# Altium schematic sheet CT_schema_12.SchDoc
size 389 x 385 mm
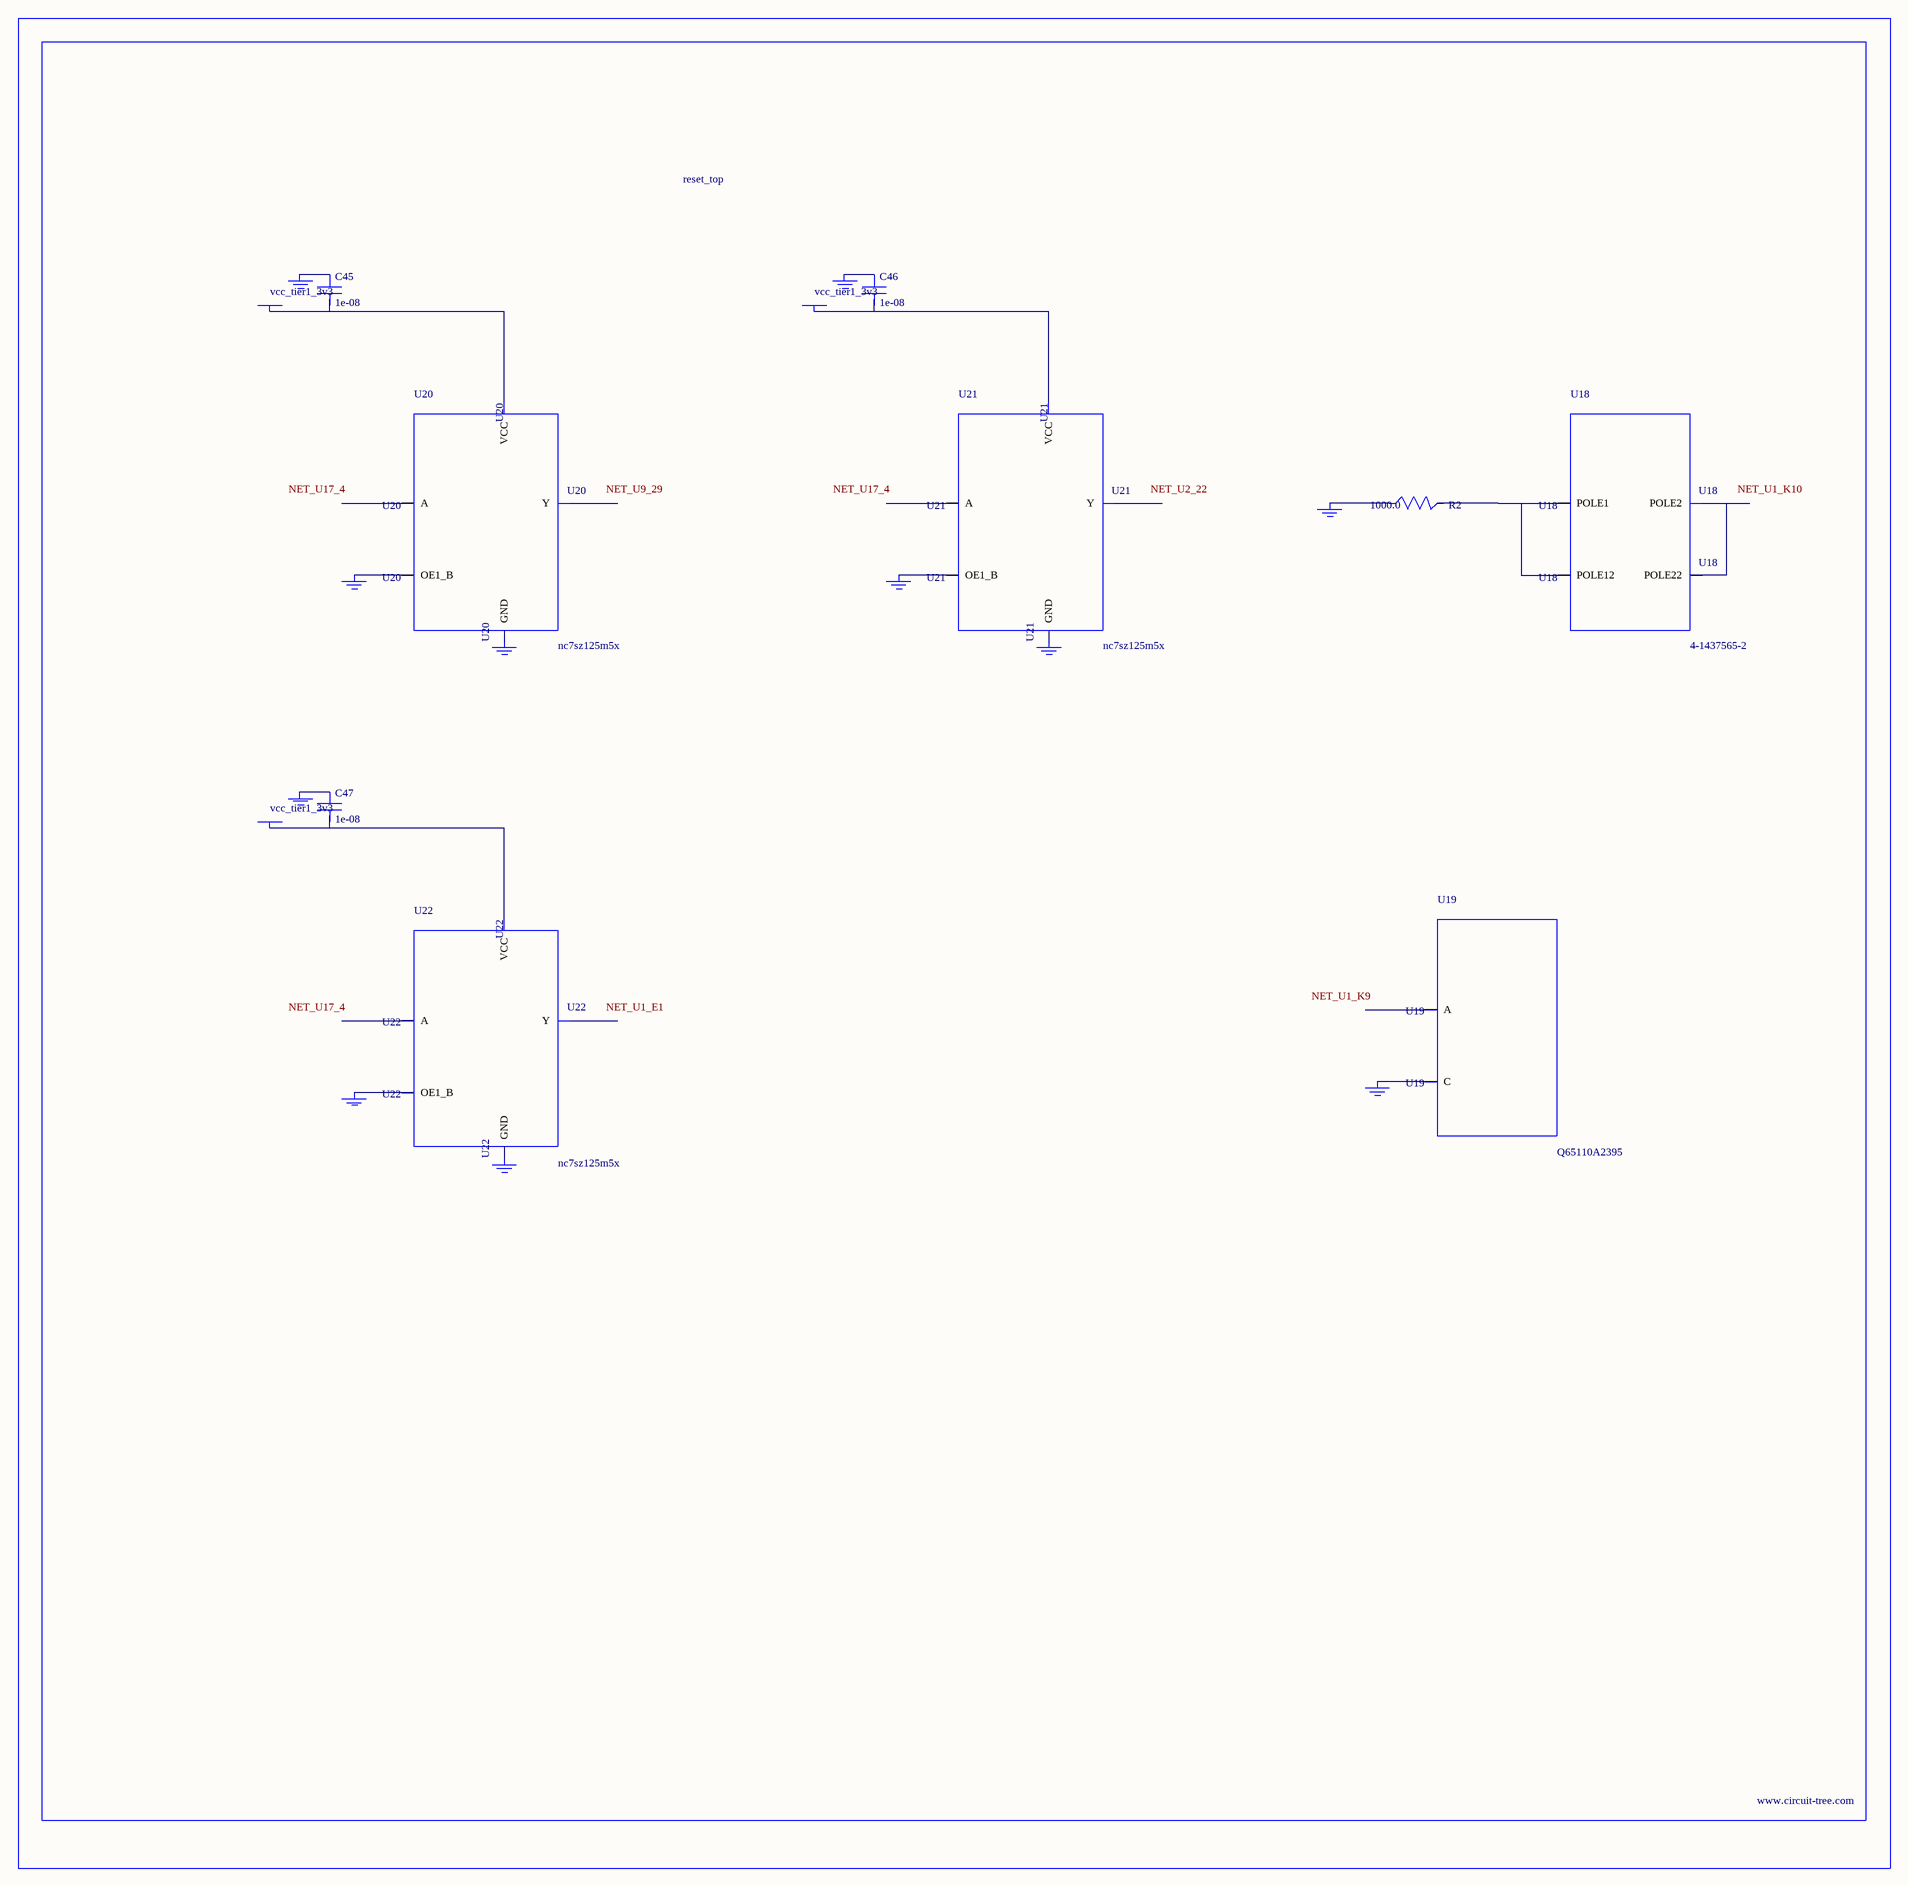
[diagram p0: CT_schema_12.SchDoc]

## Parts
BORDER11  (no value)
C45  1e-08  [C0402]
C46  1e-08  [C0402]
C47  1e-08  [C0402]
GND_INSTANCE_11_0  (no value)
GND_INSTANCE_11_1  (no value)
GND_INSTANCE_11_2  (no value)
GND_INSTANCE_11_3  (no value)
GND_INSTANCE_11_4  (no value)
GND_INSTANCE_11_5  (no value)
GND_INSTANCE_11_6  (no value)
GND_INSTANCE_11_7  (no value)
GND_INSTANCE_11_8  (no value)
GND_INSTANCE_11_9  (no value)
GND_INSTANCE_11_10  (no value)
POWER_INSTANCE_11_0  vcc_tier1_3v3
POWER_INSTANCE_11_1  vcc_tier1_3v3
POWER_INSTANCE_11_2  vcc_tier1_3v3
R2  1000.0  [R0603]
U18  4-1437565-2  [SW_4-1437565-2]
U19  Q65110A2395  [LGM67K-G1J2-24-Z]
U20  nc7sz125m5x  [NC7SZ125M5X]
U21  nc7sz125m5x  [NC7SZ125M5X]
U22  nc7sz125m5x  [NC7SZ125M5X]

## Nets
NetC45_1: C45.1 GND_INSTANCE_11_2.0(GND)
NetC45_2: C45.2 POWER_INSTANCE_11_0.0(PWR) U20.5(VCC)
NetC46_1: C46.1 GND_INSTANCE_11_5.0(GND)
NetC46_2: C46.2 POWER_INSTANCE_11_1.0(PWR) U21.5(VCC)
NetC47_1: C47.1 GND_INSTANCE_11_8.0(GND)
NetC47_2: C47.2 POWER_INSTANCE_11_2.0(PWR) U22.5(VCC)
NetGND_INSTANCE_11_0_0: GND_INSTANCE_11_0.0(GND) R2.1
NetGND_INSTANCE_11_1_0: GND_INSTANCE_11_1.0(GND) U19.C
NetGND_INSTANCE_11_3_0: GND_INSTANCE_11_3.0(GND) U20.1(OE1_B)
NetGND_INSTANCE_11_4_0: GND_INSTANCE_11_4.0(GND) U20.3(GND)
NetGND_INSTANCE_11_6_0: GND_INSTANCE_11_6.0(GND) U21.1(OE1_B)
NetGND_INSTANCE_11_7_0: GND_INSTANCE_11_7.0(GND) U21.3(GND)
NetGND_INSTANCE_11_9_0: GND_INSTANCE_11_9.0(GND) U22.1(OE1_B)
NetGND_INSTANCE_11_10_0: GND_INSTANCE_11_10.0(GND) U22.3(GND)
NetR2_2: R2.2 U18.1(POLE1) U18.2(POLE12)
NetU18_3: U18.3(POLE2) U18.4(POLE22)

Not connected (* = marked no-connect by the designer): U19 A; U20 2(A) 4(Y); U21 2(A) 4(Y); U22 2(A) 4(Y)

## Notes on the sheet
- Labels drawn without touching a wire or pin: NET_U1_E1, NET_U1_K9, NET_U1_K10, NET_U2_22, NET_U9_29, NET_U17_4

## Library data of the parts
BORDER11 = BORDER_PAGE11
C45-C47 = C0402C103K3RAC
GND_INSTANCE_11_0-GND_INSTANCE_11_10 = GND
POWER_INSTANCE_11_0-POWER_INSTANCE_11_2 = PWR
R2 = RC0603JR-071KL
